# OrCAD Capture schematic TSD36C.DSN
size A; title: TSDxxC Bidrectional TVS Diodes in SOD-323 Package; rev: 1.0; note: Datasheet: SLVSH42
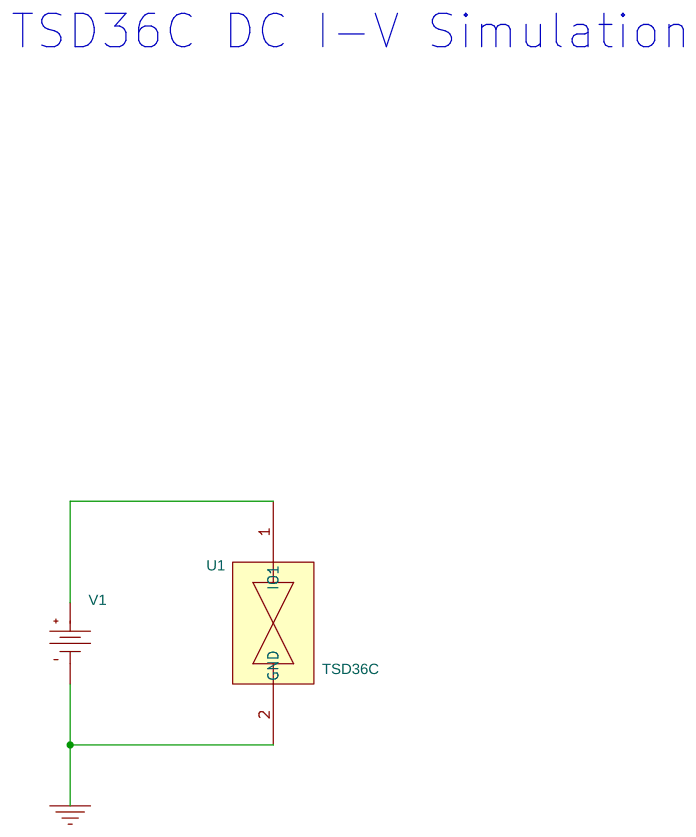
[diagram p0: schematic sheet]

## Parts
U1  TSD36C
V1  VDC

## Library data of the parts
U1 = TSD36C
V1 = VDC

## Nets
0: U1.2(GND) V1.1(-)
N02839: U1.1(IO1) V1.0(+)

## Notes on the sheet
- TSD36C DC I-V Simulation
